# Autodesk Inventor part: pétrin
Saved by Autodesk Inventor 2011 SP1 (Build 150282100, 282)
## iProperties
Created: 2010-12
Part Number: pétrin
Document SubType Name: Modeling
Designer: eric
Density: 1 g/cm^3
Mass: 7.92796 g
Surface Area: 48.5403 cm^2
Volume: 7.92796 cm^3
Author: eric
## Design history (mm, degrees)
feature "Base1"
node "Solide1"
node "Corps solides"
node "Corps surfaciques"
